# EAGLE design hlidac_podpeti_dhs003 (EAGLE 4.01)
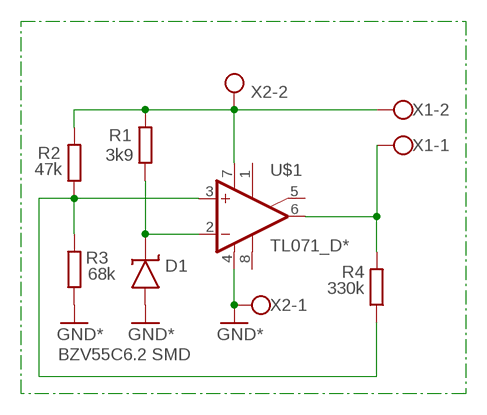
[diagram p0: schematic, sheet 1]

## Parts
D1  BZV55C6.2 SMD  BZV55C6  [SOD80]
R1  3k9  R-EU_M1206  [M1206]
R2  47k  R-EU_M1206  [M1206]
R3  68k  R-EU_M1206  [M1206]
R4  330k  R-EU_M1206  [M1206]
U$1  TL071_D*  [SO08]
X1  AK500/2  [AK500/2]
X2  AK500/2  [AK500/2]

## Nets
GND: D1.2(A) R3.1 U$1.4(V-) X2.1 ; supply symbol labelled GND*
N$1: D1.1(K) R1.1 U$1.2(-IN)
N$2: R2.1 R3.2 R4.1 U$1.3(+IN)
N$4: R1.2 R2.2 U$1.7(V+) X1.2 X2.2
N$5: R4.2 U$1.6(OUT) X1.1
Unconnected: U$1.1(ON1) U$1.5(ON2) U$1.8(OPT)

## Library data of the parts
D1 = DH_servis_1:BZV55C6
R1-R4 = rcl:R-EU_: RESISTOR, European symbol
U$1 = linear:TL071_D
X1 X2 = con-ptr500:AK500/2: CONNECTOR

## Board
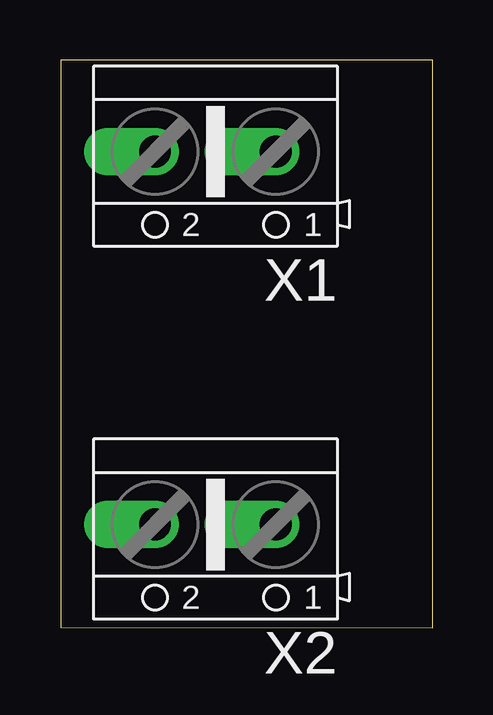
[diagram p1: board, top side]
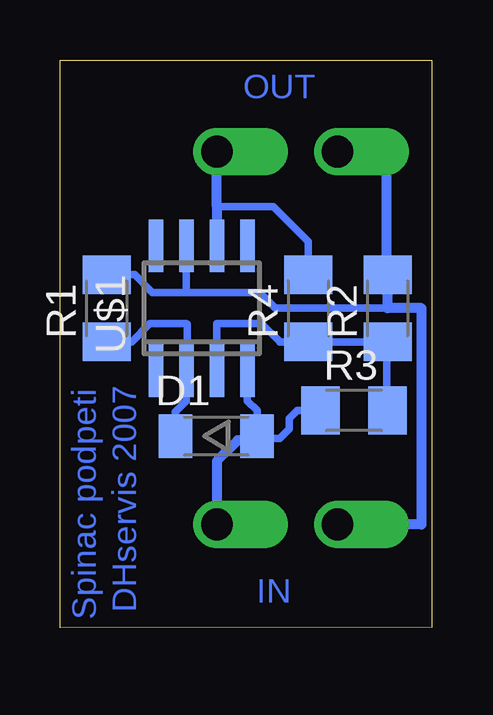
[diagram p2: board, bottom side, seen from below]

Size 15.5 x 23.67 mm. Coordinates in mm from the lower left corner, seen from the top.
Outline: 0,0.03 15.5,0 15.5,23.67 0,23.67 0,0.03
Copper layers used: Bottom

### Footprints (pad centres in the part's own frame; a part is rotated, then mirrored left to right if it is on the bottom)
SOD80 = smd 1.4 x 1.8: 1 -1.7,0; 2 1.7,0
M1206 = smd 1.6 x 2: 1 -1.4,0; 2 1.4,0
SO08 = smd 0.6 x 2.2: 1 -1.905,-2.6; 2 -0.635,-2.6; 3 0.635,-2.6; 4 1.905,-2.6; 5 1.905,2.6; 6 0.635,2.6; 7 -0.635,2.6; 8 -1.905,2.6
AK500/2 = drill 1.321 offset: 1 -2.515,0; 2 2.515,0

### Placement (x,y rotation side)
D1  8.99,7.99 0 bottom
R1  13.56,13.32 90 bottom
R2  1.85,13.32 90 bottom
R3  3.25,9.06 0 bottom
R4  5.15,13.32 90 bottom
U$1  9.6,13.32 0 bottom
X1  6.45,19.85 180 top
X2  6.45,4.31 180 top

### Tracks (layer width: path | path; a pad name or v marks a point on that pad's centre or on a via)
GND
  Bottom 0.305: U$1.4 7.69,9.46 7.28,9.05 7.28,8.01 7.28,7.96 7.23,7.91 7.26,7.89 | R3.1 5.61,9.05 5.94,8.72 5.94,8.29 6.34,7.89 7.26,7.89 | 7.26,7.89 7.31,7.84 7.34,7.81
  Bottom 0.406: 7.28,8.01 7.29,8.01 D1.2 | X2.1 8.96,6.95 8.1,7.81 7.34,7.81
  pour Bottom: -0.31,23.79 15.49,23.79 -0.23,23.71
N$1
  Bottom 0.305: D1.1 10.69,8.02 | 10.66,8.04 10.69,8.06 10.69,9 10.23,9.46 U$1.2 10.21,10.75 10.21,12.66 10.23,12.69 11.76,12.69 12.52,11.92 R1.1
  Bottom 0.406: 10.69,8.02 10.66,8.04
N$2
  Bottom 0.305: R2.1 5.1,11.92 | U$1.3 8.96,12.69 7.11,12.69 6.34,11.93 6.34,11.92 R4.1 | 1.87,9.08 1.87,11.9
  Bottom 0.406: R4.1 5.13,11.95 5.1,11.92 | R3.2 1.87,9.08 | 1.87,11.9 R2.1
N$4
  Bottom 0.305: 1.85,13.32 6.52,13.32 7.18,13.98 10.23,13.98 | 13.53,14.72 13.54,14.72 | 13.54,14.72 R1.2 | 13.53,14.72 13.53,14.77 | 13.54,14.72 13.53,14.72 | 13.53,14.72 12.39,14.72 11.65,13.98 10.23,13.98 | 13.53,14.72 | 10.23,13.98 U$1.7
  Bottom 0.406: 1.87,14.72 | 1.87,14.72 R2.2 1.85,13.32 0.43,13.32 0.43,4.31 X2.2 | X1.2 1.87,19.85 1.87,14.72
N$5
  Bottom 0.305: 8.99,15.92 8.99,15.89 | U$1.6 8.96,15.86 | R4.2 5.15,16.09 6.62,17.56 8.96,17.56
  Bottom 0.406: 8.99,15.92 U$1.6 8.96,17.56 X1.1

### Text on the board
Bottom: OUT | DHservis 2007 | Spinac podpeti | IN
